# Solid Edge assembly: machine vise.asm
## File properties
Author: Robert a Rhodes jr
Template: Normal.asm
Last saved by: Administrator
Revision: 23
Application: Solid Edge
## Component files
slide key.par
base.par
Sliding jaw.par
vise screw.par
collar.par
handle rod.par
handle ball.par
jaw plate.par
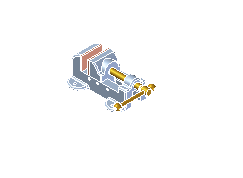
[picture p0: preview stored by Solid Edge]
